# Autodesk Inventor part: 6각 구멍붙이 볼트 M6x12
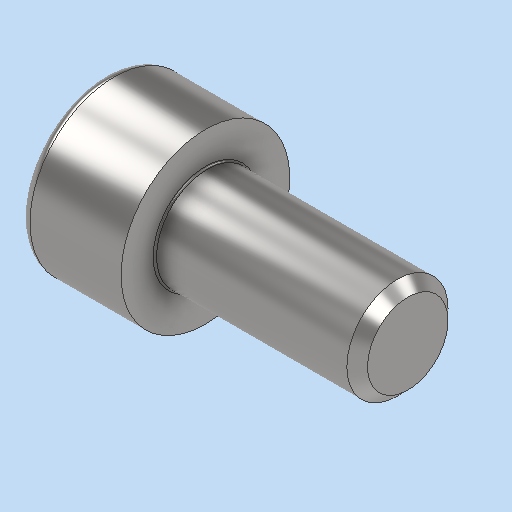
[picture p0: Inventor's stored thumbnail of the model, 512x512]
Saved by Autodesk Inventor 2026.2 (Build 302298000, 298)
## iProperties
Created: 2026-01
Part Number: 6각 구멍붙이 볼트 M6x12
Material: 강철, 연강
Description: 6각머리 태핑 나사
Document SubType Name: Modeling
Designer: PC2-07
Density: 7.85 g/cm^3
Appearance: 기본값
Sending System: Autodesk Inventor 2026
Preprocessor: ST-DEVELOPER v20.1
Author: jhkim
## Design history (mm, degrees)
feature "Solid1"
node "솔리드1"
